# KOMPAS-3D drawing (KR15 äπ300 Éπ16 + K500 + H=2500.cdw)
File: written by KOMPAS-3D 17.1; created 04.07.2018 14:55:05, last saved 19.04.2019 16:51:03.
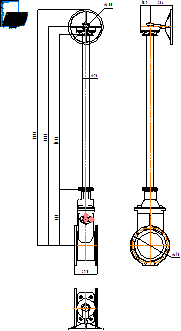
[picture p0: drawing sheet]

Sheet 1: A4, portrait

Title block, sheet 1: name: KR15 Ду300 Ру16 + / K500 + H=2500; material: Внимание! Данный продукт является объектом авторского права ООО «Торговый Дом АДЛ». / Запрещается изменение, копирование, распространение / (в том числе путем копирования на другие сайты и ресурсы в Интернете) / или любое иное использование информации и объектов без предварительного / согласия правообладателя (ООО «Торговый Дом АДЛ»).; mass: 36,7; sheets: 1; organisation: ООО "Торговый дом АДЛ"; sheet format: A4; stored path: \\adlc.lan\data\АДЛ_ПКД\3D-модели\ADL production\Клиновые задвижки серии KR ГРАНАР\Клиновые задвижки KR15 со стационарным удлинением\KOMPAS 2D\KR15 Ду300 Ру16 + K500 + H=2500.cdw

Views: Проекционный вид 6, Спереди 11, Проекционный вид 12
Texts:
  kka
  adl
Dimensions and other numbers on the sheet: 2500; 1770; 2696; 400; 76; 645; 270; 109; 410; 254; 1:1; 1; 36,7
